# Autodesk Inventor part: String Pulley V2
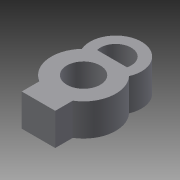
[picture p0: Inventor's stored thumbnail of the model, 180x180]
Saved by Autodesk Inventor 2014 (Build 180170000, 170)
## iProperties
Created: 2013-12
Part Number: String Pulley V2
Material: Generic
Document SubType Name: Modeling
Designer: 603839
Density: 1 g/cm^3
Appearance: Default
Author: 603839
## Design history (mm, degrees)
sketch "Sketch1"
  geometry: C1 r 3.302 at (0, 0); C2 r 6.35 at (0, 0); 1 further point
  constraints: 2 centre point, 2 coincident
  dimensions: "d0" = 6.604 diameter of C1; "d1" = 12.7 diameter of C2
extrude "Extrusion1" new body sketch "Sketch1" distance "d2" = 6.35; taper "d3" = 0 deg
sketch "Sketch3"
  geometry: L1 (-3.302, 0)-(-3.302, -8.89); L2 (3.302, 0)-(3.302, -8.89); L3 (3.302, -8.89)-(-3.302, -8.89); A1 r 3.302 centre (0, 0) between (-3.302, 0) and (3.302, 0) reference
  constraints: 6 end point, 2 point on circle, 2 tangent, 1 parallel, 1 vertical
  dimensions: "d4" = 8.89 distance of L1.start L1.end; "d5" = 8.89 distance of L2.start L2.end
extrude "Extrusion2" join sketch "Sketch3" stored distance "d6" = 6.35; taper "d7" = 0 deg
sketch "Sketch4"
  geometry: C1 r 3.302 at (0, 0) reference; A1 r 6.35 centre (0, 0) between (3.302, -5.424) and (-3.302, -5.424) reference; A2 r 3.048 centre (0, 6.35) between (2.959, 5.618) and (-2.959, 5.618); A3 r 5.08 centre (0, 6.35) between (4.656, 4.318) and (-4.656, 4.318); A4 r 6.35 centre (0, 0) between (-2.959, 5.618) and (-4.656, 4.318); A5 r 6.35 centre (0, 0) between (4.656, 4.318) and (2.959, 5.618)
  constraints: 14 point on circle, 4 centre point, 2 concentric, 1 tangent
  dimensions: "d9" = 10.16 diameter of A3
extrude "Extrusion3" join sketch "Sketch4" stored distance "d10" = 6.35; taper "d11" = 0 deg
sketch "Sketch5"
  geometry: L1 (3.302, -8.89)-(3.302, -5.424) reference; L2 (-2.959, 5.618)-(2.959, 5.618); A1 r 6.35 centre (0, 0) between (2.959, 5.618) and (-2.959, 5.618) reference
  constraints: 2 end point, 1 perpendicular
extrude "Extrusion4" cut sketch "Sketch5" distance "d12" = 6.35; taper "d13" = 0 deg
body "Solid1"
